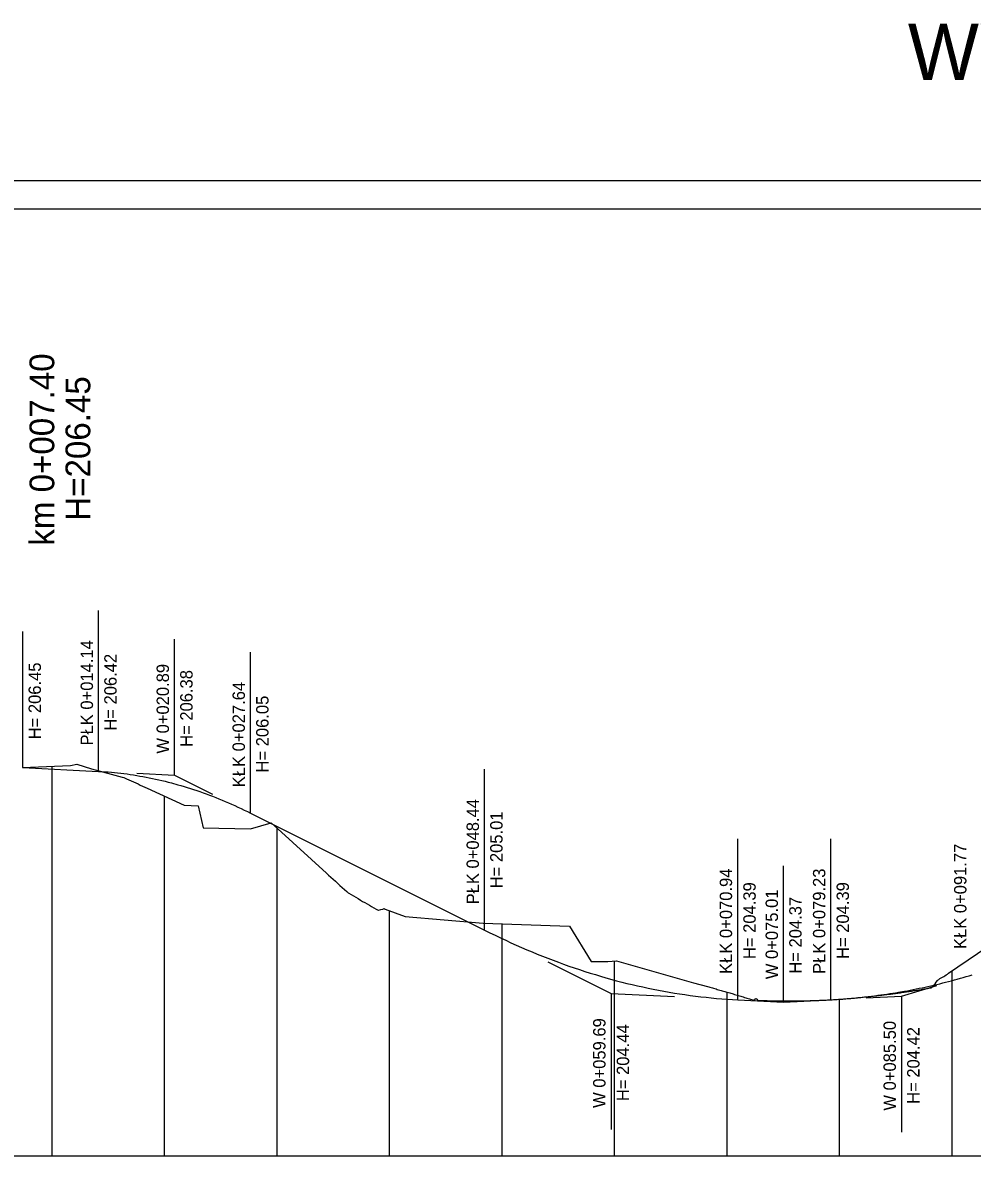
# Model space of a CAD drawing. Extents: x 6513080 to 6513380, y 6022307 to 6022469.
# Drawn here: x 6513125.1 to 6513209.5, y 6022367.3 to 6022469.3 of the extents above; entities that cross this region are included whole.
import ezdxf

# ---------------------------------------------------------------- set-up
doc = ezdxf.new("R2010")
doc.units = 0
for name, color, linetype in [('1', 7, 'Continuous'), ('42', 7, 'Continuous'), ('CONSTRUCTION_CLASS', 7, 'Continuous'), ('maxp_opisy', 7, 'Continuous'), ('maxp_ramka_2', 7, 'Continuous')]:
    doc.layers.add(name, color=color, linetype=linetype)

msp = doc.modelspace()

# ---------------------------------------------------------------- linework, layer by layer
for p, q in [((6513125.11, 6022403.07), (6513131.84, 6022402.73)), ((6513125.11, 6022403.07), (6513131.84, 6022402.73)), ((6513145.34, 6022399.02), (6513166.14, 6022388.62)), ((6513145.34, 6022399.02), (6513166.14, 6022388.62)), ((6513188.64, 6022382.43), (6513192.72, 6022382.23)), ((6513188.64, 6022382.43), (6513192.72, 6022382.23)), ((6513192.72, 6022382.23), (6513196.93, 6022382.44)), ((6513192.72, 6022382.23), (6513196.93, 6022382.44))]:
    msp.add_line(p, q)
for points in [[(6513131.84, 6022402.73), (6513132.12, 6022402.71), (6513132.41, 6022402.7), (6513132.69, 6022402.68), (6513132.97, 6022402.65), (6513133.25, 6022402.63), (6513133.53, 6022402.6), (6513133.81, 6022402.57), (6513134.09, 6022402.53), (6513134.37, 6022402.5), (6513134.65, 6022402.46), (6513134.94, 6022402.42), (6513135.22, 6022402.37), (6513135.5, 6022402.32), (6513135.78, 6022402.28), (6513136.06, 6022402.22), (6513136.34, 6022402.17), (6513136.62, 6022402.11), (6513136.9, 6022402.05), (6513137.19, 6022401.99), (6513137.47, 6022401.92), (6513137.75, 6022401.85), (6513138.03, 6022401.78), (6513138.31, 6022401.71), (6513138.87, 6022401.55), (6513139.15, 6022401.47), (6513139.43, 6022401.39), (6513139.72, 6022401.3), (6513140, 6022401.21), (6513140.28, 6022401.12), (6513140.56, 6022401.03), (6513140.84, 6022400.93), (6513141.12, 6022400.83), (6513141.4, 6022400.73), (6513141.68, 6022400.62), (6513141.97, 6022400.52), (6513142.25, 6022400.41), (6513142.53, 6022400.29), (6513142.81, 6022400.18), (6513143.09, 6022400.06), (6513143.37, 6022399.94), (6513143.65, 6022399.81), (6513143.93, 6022399.69), (6513144.21, 6022399.56), (6513144.5, 6022399.43), (6513144.78, 6022399.29), (6513145.06, 6022399.16), (6513145.34, 6022399.02)], [(6513131.84, 6022402.73), (6513132.12, 6022402.71), (6513132.41, 6022402.7), (6513132.69, 6022402.68), (6513132.97, 6022402.65), (6513133.25, 6022402.63), (6513133.53, 6022402.6), (6513133.81, 6022402.57), (6513134.09, 6022402.53), (6513134.37, 6022402.5), (6513134.65, 6022402.46), (6513134.94, 6022402.42), (6513135.22, 6022402.37), (6513135.5, 6022402.32), (6513135.78, 6022402.28), (6513136.06, 6022402.22), (6513136.34, 6022402.17), (6513136.62, 6022402.11), (6513136.9, 6022402.05), (6513137.19, 6022401.99), (6513137.47, 6022401.92), (6513137.75, 6022401.85), (6513138.03, 6022401.78), (6513138.31, 6022401.71), (6513138.87, 6022401.55), (6513139.15, 6022401.47), (6513139.43, 6022401.39), (6513139.72, 6022401.3), (6513140, 6022401.21), (6513140.28, 6022401.12), (6513140.56, 6022401.03), (6513140.84, 6022400.93), (6513141.12, 6022400.83), (6513141.4, 6022400.73), (6513141.68, 6022400.62), (6513141.97, 6022400.52), (6513142.25, 6022400.41), (6513142.53, 6022400.29), (6513142.81, 6022400.18), (6513143.09, 6022400.06), (6513143.37, 6022399.94), (6513143.65, 6022399.81), (6513143.93, 6022399.69), (6513144.21, 6022399.56), (6513144.5, 6022399.43), (6513144.78, 6022399.29), (6513145.06, 6022399.16), (6513145.34, 6022399.02)], [(6513166.14, 6022388.62), (6513166.61, 6022388.39), (6513167.08, 6022388.16), (6513167.55, 6022387.93), (6513168.02, 6022387.72), (6513168.49, 6022387.5), (6513168.96, 6022387.29), (6513169.42, 6022387.09), (6513169.89, 6022386.88), (6513170.36, 6022386.69), (6513170.83, 6022386.49), (6513171.3, 6022386.31), (6513171.77, 6022386.12), (6513172.24, 6022385.94), (6513172.7, 6022385.77), (6513173.17, 6022385.6), (6513173.64, 6022385.43), (6513174.11, 6022385.27), (6513174.58, 6022385.11), (6513175.05, 6022384.96), (6513175.52, 6022384.81), (6513175.99, 6022384.67), (6513176.45, 6022384.53), (6513176.92, 6022384.39), (6513177.86, 6022384.13), (6513178.33, 6022384.01), (6513178.8, 6022383.89), (6513179.27, 6022383.78), (6513179.73, 6022383.67), (6513180.2, 6022383.57), (6513180.67, 6022383.47), (6513181.14, 6022383.37), (6513181.61, 6022383.28), (6513182.08, 6022383.19), (6513182.55, 6022383.11), (6513183.01, 6022383.03), (6513183.48, 6022382.96), (6513183.95, 6022382.89), (6513184.42, 6022382.82), (6513184.89, 6022382.76), (6513185.36, 6022382.7), (6513185.83, 6022382.65), (6513186.29, 6022382.6), (6513186.76, 6022382.56), (6513187.23, 6022382.52), (6513187.7, 6022382.49), (6513188.17, 6022382.46), (6513188.64, 6022382.43)], [(6513166.14, 6022388.62), (6513166.61, 6022388.39), (6513167.08, 6022388.16), (6513167.55, 6022387.93), (6513168.02, 6022387.72), (6513168.49, 6022387.5), (6513168.96, 6022387.29), (6513169.42, 6022387.09), (6513169.89, 6022386.88), (6513170.36, 6022386.69), (6513170.83, 6022386.49), (6513171.3, 6022386.31), (6513171.77, 6022386.12), (6513172.24, 6022385.94), (6513172.7, 6022385.77), (6513173.17, 6022385.6), (6513173.64, 6022385.43), (6513174.11, 6022385.27), (6513174.58, 6022385.11), (6513175.05, 6022384.96), (6513175.52, 6022384.81), (6513175.99, 6022384.67), (6513176.45, 6022384.53), (6513176.92, 6022384.39), (6513177.86, 6022384.13), (6513178.33, 6022384.01), (6513178.8, 6022383.89), (6513179.27, 6022383.78), (6513179.73, 6022383.67), (6513180.2, 6022383.57), (6513180.67, 6022383.47), (6513181.14, 6022383.37), (6513181.61, 6022383.28), (6513182.08, 6022383.19), (6513182.55, 6022383.11), (6513183.01, 6022383.03), (6513183.48, 6022382.96), (6513183.95, 6022382.89), (6513184.42, 6022382.82), (6513184.89, 6022382.76), (6513185.36, 6022382.7), (6513185.83, 6022382.65), (6513186.29, 6022382.6), (6513186.76, 6022382.56), (6513187.23, 6022382.52), (6513187.7, 6022382.49), (6513188.17, 6022382.46), (6513188.64, 6022382.43)], [(6513196.93, 6022382.44), (6513197.19, 6022382.45), (6513197.45, 6022382.47), (6513197.71, 6022382.49), (6513197.97, 6022382.5), (6513198.24, 6022382.52), (6513198.5, 6022382.54), (6513198.76, 6022382.57), (6513199.02, 6022382.59), (6513199.28, 6022382.61), (6513199.54, 6022382.64), (6513199.8, 6022382.67), (6513200.06, 6022382.7), (6513200.33, 6022382.73), (6513200.59, 6022382.76), (6513200.85, 6022382.79), (6513201.11, 6022382.83), (6513201.37, 6022382.86), (6513201.63, 6022382.9), (6513201.89, 6022382.94), (6513202.15, 6022382.98), (6513202.42, 6022383.02), (6513202.68, 6022383.06), (6513202.94, 6022383.1), (6513203.46, 6022383.2), (6513203.72, 6022383.24), (6513203.98, 6022383.29), (6513204.24, 6022383.34), (6513204.51, 6022383.4), (6513204.77, 6022383.45), (6513205.03, 6022383.5), (6513205.29, 6022383.56), (6513205.55, 6022383.62), (6513205.81, 6022383.68), (6513206.07, 6022383.74), (6513206.34, 6022383.8), (6513206.6, 6022383.86), (6513206.86, 6022383.93), (6513207.12, 6022383.99), (6513207.38, 6022384.06), (6513207.64, 6022384.13), (6513207.9, 6022384.2), (6513208.16, 6022384.27), (6513208.43, 6022384.34), (6513208.69, 6022384.42), (6513208.95, 6022384.49), (6513209.21, 6022384.57), (6513209.47, 6022384.65)], [(6513196.93, 6022382.44), (6513197.19, 6022382.45), (6513197.45, 6022382.47), (6513197.71, 6022382.49), (6513197.97, 6022382.5), (6513198.24, 6022382.52), (6513198.5, 6022382.54), (6513198.76, 6022382.57), (6513199.02, 6022382.59), (6513199.28, 6022382.61), (6513199.54, 6022382.64), (6513199.8, 6022382.67), (6513200.06, 6022382.7), (6513200.33, 6022382.73), (6513200.59, 6022382.76), (6513200.85, 6022382.79), (6513201.11, 6022382.83), (6513201.37, 6022382.86), (6513201.63, 6022382.9), (6513201.89, 6022382.94), (6513202.15, 6022382.98), (6513202.42, 6022383.02), (6513202.68, 6022383.06), (6513202.94, 6022383.1), (6513203.46, 6022383.2), (6513203.72, 6022383.24), (6513203.98, 6022383.29), (6513204.24, 6022383.34), (6513204.51, 6022383.4), (6513204.77, 6022383.45), (6513205.03, 6022383.5), (6513205.29, 6022383.56), (6513205.55, 6022383.62), (6513205.81, 6022383.68), (6513206.07, 6022383.74), (6513206.34, 6022383.8), (6513206.6, 6022383.86), (6513206.86, 6022383.93), (6513207.12, 6022383.99), (6513207.38, 6022384.06), (6513207.64, 6022384.13), (6513207.9, 6022384.2), (6513208.16, 6022384.27), (6513208.43, 6022384.34), (6513208.69, 6022384.42), (6513208.95, 6022384.49), (6513209.21, 6022384.57), (6513209.47, 6022384.65)]]:
    msp.add_lwpolyline(points)
at = {"layer": '1'}
for p, q in [((6513127.7, 6022368.56), (6513127.7, 6022403.19)), ((6513135.22, 6022402.56), (6513138.59, 6022402.39)), ((6513138.59, 6022402.39), (6513141.97, 6022400.71)), ((6513137.7, 6022368.56), (6513137.7, 6022400.53)), ((6513147.7, 6022368.56), (6513147.7, 6022397.7)), ((6513157.7, 6022368.56), (6513157.7, 6022390.34)), ((6513167.7, 6022368.56), (6513167.7, 6022389.18)), ((6513177.7, 6022368.56), (6513177.7, 6022385.87)), ((6513171.77, 6022385.81), (6513177.39, 6022383)), ((6513207.7, 6022368.56), (6513207.7, 6022385)), ((6513177.39, 6022383), (6513183.01, 6022382.71)), ((6513187.7, 6022368.56), (6513187.7, 6022383.11)), ((6513203.2, 6022382.76), (6513206.34, 6022383.7)), ((6513197.7, 6022368.56), (6513197.7, 6022382.49)), ((6513200.06, 6022382.6), (6513203.2, 6022382.76)), ((6513127.7, 6022368.56), (6513127.7, 6022369.56)), ((6513137.7, 6022368.56), (6513137.7, 6022369.56)), ((6513147.7, 6022368.56), (6513147.7, 6022369.56)), ((6513157.7, 6022368.56), (6513157.7, 6022369.56)), ((6513167.7, 6022368.56), (6513167.7, 6022369.56)), ((6513177.7, 6022368.56), (6513177.7, 6022369.56)), ((6513187.7, 6022368.56), (6513187.7, 6022369.56)), ((6513197.7, 6022368.56), (6513197.7, 6022369.56)), ((6513207.7, 6022368.56), (6513207.7, 6022369.56)), ((6513117.7, 6022368.56), (6513327.7, 6022368.56))]:
    msp.add_line(p, q, dxfattribs=at)
msp.add_lwpolyline([(6513125.08, 6022403.07), (6513129.34, 6022403.24), (6513129.9, 6022403.38), (6513131.2, 6022402.95), (6513133.93, 6022402.23), (6513134.09, 6022402.19), (6513134.13, 6022402.17), (6513134.33, 6022402.08), (6513134.53, 6022401.99), (6513134.74, 6022401.89), (6513134.94, 6022401.8), (6513135.14, 6022401.71), (6513135.34, 6022401.62), (6513135.54, 6022401.52), (6513135.74, 6022401.43), (6513135.94, 6022401.34), (6513136.15, 6022401.24), (6513139.43, 6022399.72), (6513140.7, 6022399.68), (6513141.13, 6022397.7), (6513145.35, 6022397.63), (6513147.18, 6022398.17), (6513147.78, 6022397.63), (6513152.08, 6022393.69), (6513152.28, 6022393.51), (6513152.48, 6022393.33), (6513152.69, 6022393.15), (6513152.89, 6022392.96), (6513153.09, 6022392.78), (6513153.29, 6022392.6), (6513153.49, 6022392.42), (6513153.69, 6022392.24), (6513153.89, 6022392.06), (6513154.03, 6022391.94), (6513154.09, 6022391.9), (6513154.29, 6022391.78), (6513154.49, 6022391.66), (6513154.7, 6022391.54), (6513154.9, 6022391.42), (6513155.1, 6022391.3), (6513155.3, 6022391.18), (6513155.5, 6022391.07), (6513155.7, 6022390.95), (6513155.9, 6022390.84), (6513156.1, 6022390.72), (6513156.3, 6022390.61), (6513156.5, 6022390.5), (6513156.69, 6022390.39), (6513156.71, 6022390.4), (6513156.91, 6022390.45), (6513157.11, 6022390.5), (6513157.22, 6022390.53), (6513157.31, 6022390.49), (6513159.07, 6022389.82), (6513166.02, 6022389.23), (6513173.68, 6022388.98), (6513175.61, 6022385.83), (6513177.11, 6022385.82), (6513177.88, 6022385.89), (6513184.7, 6022383.94), (6513185.95, 6022383.61), (6513186.06, 6022383.58), (6513186.17, 6022383.55), (6513186.28, 6022383.52), (6513186.39, 6022383.49), (6513186.5, 6022383.46), (6513186.61, 6022383.43), (6513186.72, 6022383.4), (6513186.83, 6022383.36), (6513186.94, 6022383.33), (6513187.05, 6022383.3), (6513187.16, 6022383.27), (6513187.27, 6022383.24), (6513187.38, 6022383.21), (6513187.49, 6022383.18), (6513187.6, 6022383.14), (6513187.71, 6022383.11), (6513187.82, 6022383.08), (6513187.93, 6022383.05), (6513188.04, 6022383.01), (6513188.15, 6022382.98), (6513188.25, 6022382.95), (6513188.36, 6022382.91), (6513188.47, 6022382.88), (6513188.58, 6022382.85), (6513188.69, 6022382.81), (6513188.8, 6022382.78), (6513188.91, 6022382.74), (6513189.02, 6022382.71), (6513189.13, 6022382.68), (6513189.24, 6022382.64), (6513189.35, 6022382.61), (6513189.37, 6022382.6), (6513189.46, 6022382.58), (6513189.57, 6022382.54), (6513189.68, 6022382.51), (6513189.79, 6022382.48), (6513189.9, 6022382.45), (6513190.01, 6022382.42), (6513190.05, 6022382.41), (6513190.12, 6022382.4), (6513190.14, 6022382.4), (6513190.23, 6022382.51), (6513190.28, 6022382.56), (6513190.34, 6022382.49), (6513190.44, 6022382.38), (6513190.45, 6022382.38), (6513190.56, 6022382.38), (6513190.67, 6022382.37), (6513190.78, 6022382.37), (6513190.89, 6022382.37), (6513191, 6022382.36), (6513191.11, 6022382.36), (6513191.22, 6022382.36), (6513191.33, 6022382.35), (6513191.44, 6022382.35), (6513191.55, 6022382.35), (6513191.66, 6022382.34), (6513191.77, 6022382.34), (6513191.88, 6022382.34), (6513191.99, 6022382.34), (6513192.1, 6022382.34), (6513192.21, 6022382.33), (6513192.32, 6022382.33), (6513192.43, 6022382.33), (6513192.54, 6022382.33), (6513192.65, 6022382.33), (6513192.76, 6022382.33), (6513192.87, 6022382.33), (6513192.98, 6022382.33), (6513193.09, 6022382.33), (6513193.2, 6022382.33), (6513193.31, 6022382.33), (6513193.42, 6022382.33), (6513193.53, 6022382.33), (6513193.64, 6022382.33), (6513193.75, 6022382.33), (6513193.86, 6022382.33), (6513193.97, 6022382.33), (6513194.08, 6022382.33), (6513194.19, 6022382.34), (6513194.3, 6022382.34), (6513194.41, 6022382.34), (6513194.52, 6022382.34), (6513194.63, 6022382.34), (6513194.74, 6022382.35), (6513194.85, 6022382.35), (6513194.96, 6022382.35), (6513195.07, 6022382.36), (6513195.18, 6022382.36), (6513195.29, 6022382.36), (6513195.4, 6022382.37), (6513195.51, 6022382.37), (6513195.62, 6022382.37), (6513195.73, 6022382.38), (6513195.84, 6022382.38), (6513195.95, 6022382.39), (6513196.06, 6022382.39), (6513196.17, 6022382.4), (6513196.28, 6022382.4), (6513196.39, 6022382.41), (6513196.5, 6022382.41), (6513196.61, 6022382.42), (6513196.72, 6022382.43), (6513196.83, 6022382.43), (6513196.94, 6022382.44), (6513197.05, 6022382.44), (6513197.16, 6022382.45), (6513197.27, 6022382.46), (6513197.38, 6022382.47), (6513197.49, 6022382.47), (6513197.6, 6022382.48), (6513197.71, 6022382.49), (6513197.82, 6022382.5), (6513197.93, 6022382.5), (6513198.04, 6022382.51), (6513198.15, 6022382.52), (6513198.26, 6022382.53), (6513198.37, 6022382.54), (6513198.48, 6022382.55), (6513198.59, 6022382.55), (6513198.7, 6022382.56), (6513198.81, 6022382.57), (6513198.92, 6022382.58), (6513199.03, 6022382.59), (6513199.14, 6022382.6), (6513199.25, 6022382.61), (6513199.36, 6022382.62), (6513199.47, 6022382.63), (6513199.58, 6022382.64), (6513199.69, 6022382.65), (6513199.8, 6022382.66), (6513199.91, 6022382.68), (6513200.02, 6022382.69), (6513200.13, 6022382.7), (6513200.24, 6022382.71), (6513200.35, 6022382.72), (6513200.46, 6022382.73), (6513200.57, 6022382.74), (6513200.68, 6022382.76), (6513200.79, 6022382.77), (6513200.9, 6022382.78), (6513201.01, 6022382.79), (6513201.12, 6022382.81), (6513201.23, 6022382.82), (6513201.34, 6022382.83), (6513201.45, 6022382.85), (6513201.56, 6022382.86), (6513201.67, 6022382.87), (6513201.78, 6022382.89), (6513201.89, 6022382.9), (6513202, 6022382.92), (6513202.11, 6022382.93), (6513202.22, 6022382.94), (6513202.33, 6022382.96), (6513202.44, 6022382.97), (6513202.55, 6022382.99), (6513202.66, 6022383), (6513202.77, 6022383.02), (6513202.88, 6022383.03), (6513202.99, 6022383.05), (6513203.1, 6022383.06), (6513203.21, 6022383.08), (6513203.32, 6022383.1), (6513203.43, 6022383.11), (6513203.54, 6022383.13), (6513203.65, 6022383.14), (6513203.76, 6022383.16), (6513203.87, 6022383.18), (6513203.98, 6022383.19), (6513204.09, 6022383.21), (6513204.2, 6022383.23), (6513204.31, 6022383.25), (6513204.42, 6022383.26), (6513204.53, 6022383.28), (6513204.64, 6022383.3), (6513204.75, 6022383.32), (6513204.86, 6022383.33), (6513204.97, 6022383.35), (6513205.08, 6022383.37), (6513205.19, 6022383.39), (6513205.3, 6022383.41), (6513205.41, 6022383.42), (6513205.52, 6022383.44), (6513205.63, 6022383.46), (6513205.74, 6022383.48), (6513205.85, 6022383.5), (6513205.9, 6022383.51), (6513205.96, 6022383.58), (6513206.07, 6022383.72), (6513206.18, 6022383.85), (6513206.29, 6022383.99), (6513206.4, 6022384.14), (6513206.46, 6022384.21), (6513206.51, 6022384.24), (6513206.62, 6022384.31), (6513206.73, 6022384.37), (6513206.84, 6022384.44), (6513206.95, 6022384.5), (6513207.06, 6022384.57), (6513207.17, 6022384.64), (6513207.28, 6022384.72), (6513207.39, 6022384.79), (6513214.28, 6022389.47)], dxfattribs=at)
at = {"layer": '42'}
for p, q in [((6513131.84, 6022402.73), (6513131.84, 6022417.03)), ((6513125.11, 6022403.07), (6513125.11, 6022415.17)), ((6513138.59, 6022402.39), (6513138.59, 6022414.49)), ((6513145.34, 6022399.02), (6513145.34, 6022413.32)), ((6513125.11, 6022403.07), (6513131.84, 6022402.73)), ((6513166.14, 6022388.62), (6513166.14, 6022402.92)), ((6513145.34, 6022399.02), (6513166.14, 6022388.62)), ((6513188.64, 6022382.43), (6513188.64, 6022396.73)), ((6513196.93, 6022382.44), (6513196.93, 6022396.74)), ((6513192.72, 6022382.23), (6513192.72, 6022394.33)), ((6513177.39, 6022383), (6513177.39, 6022370.9)), ((6513188.64, 6022382.43), (6513192.72, 6022382.23)), ((6513192.72, 6022382.23), (6513196.93, 6022382.44)), ((6513203.2, 6022382.76), (6513203.2, 6022370.66))]:
    msp.add_line(p, q, dxfattribs=at)
for points in [[(6513131.84, 6022402.73), (6513132.12, 6022402.71), (6513132.41, 6022402.7), (6513132.69, 6022402.68), (6513132.97, 6022402.65), (6513133.25, 6022402.63), (6513133.53, 6022402.6), (6513133.81, 6022402.57), (6513134.09, 6022402.53), (6513134.37, 6022402.5), (6513134.65, 6022402.46), (6513134.94, 6022402.42), (6513135.22, 6022402.37), (6513135.5, 6022402.32), (6513135.78, 6022402.28), (6513136.06, 6022402.22), (6513136.34, 6022402.17), (6513136.62, 6022402.11), (6513136.9, 6022402.05), (6513137.19, 6022401.99), (6513137.47, 6022401.92), (6513137.75, 6022401.85), (6513138.03, 6022401.78), (6513138.31, 6022401.71), (6513138.87, 6022401.55), (6513139.15, 6022401.47), (6513139.43, 6022401.39), (6513139.72, 6022401.3), (6513140, 6022401.21), (6513140.28, 6022401.12), (6513140.56, 6022401.03), (6513140.84, 6022400.93), (6513141.12, 6022400.83), (6513141.4, 6022400.73), (6513141.68, 6022400.62), (6513141.97, 6022400.52), (6513142.25, 6022400.41), (6513142.53, 6022400.29), (6513142.81, 6022400.18), (6513143.09, 6022400.06), (6513143.37, 6022399.94), (6513143.65, 6022399.81), (6513143.93, 6022399.69), (6513144.21, 6022399.56), (6513144.5, 6022399.43), (6513144.78, 6022399.29), (6513145.06, 6022399.16), (6513145.34, 6022399.02)], [(6513166.14, 6022388.62), (6513166.61, 6022388.39), (6513167.08, 6022388.16), (6513167.55, 6022387.93), (6513168.02, 6022387.72), (6513168.49, 6022387.5), (6513168.96, 6022387.29), (6513169.42, 6022387.09), (6513169.89, 6022386.88), (6513170.36, 6022386.69), (6513170.83, 6022386.49), (6513171.3, 6022386.31), (6513171.77, 6022386.12), (6513172.24, 6022385.94), (6513172.7, 6022385.77), (6513173.17, 6022385.6), (6513173.64, 6022385.43), (6513174.11, 6022385.27), (6513174.58, 6022385.11), (6513175.05, 6022384.96), (6513175.52, 6022384.81), (6513175.99, 6022384.67), (6513176.45, 6022384.53), (6513176.92, 6022384.39), (6513177.86, 6022384.13), (6513178.33, 6022384.01), (6513178.8, 6022383.89), (6513179.27, 6022383.78), (6513179.73, 6022383.67), (6513180.2, 6022383.57), (6513180.67, 6022383.47), (6513181.14, 6022383.37), (6513181.61, 6022383.28), (6513182.08, 6022383.19), (6513182.55, 6022383.11), (6513183.01, 6022383.03), (6513183.48, 6022382.96), (6513183.95, 6022382.89), (6513184.42, 6022382.82), (6513184.89, 6022382.76), (6513185.36, 6022382.7), (6513185.83, 6022382.65), (6513186.29, 6022382.6), (6513186.76, 6022382.56), (6513187.23, 6022382.52), (6513187.7, 6022382.49), (6513188.17, 6022382.46), (6513188.64, 6022382.43)], [(6513196.93, 6022382.44), (6513197.19, 6022382.45), (6513197.45, 6022382.47), (6513197.71, 6022382.49), (6513197.97, 6022382.5), (6513198.24, 6022382.52), (6513198.5, 6022382.54), (6513198.76, 6022382.57), (6513199.02, 6022382.59), (6513199.28, 6022382.61), (6513199.54, 6022382.64), (6513199.8, 6022382.67), (6513200.06, 6022382.7), (6513200.33, 6022382.73), (6513200.59, 6022382.76), (6513200.85, 6022382.79), (6513201.11, 6022382.83), (6513201.37, 6022382.86), (6513201.63, 6022382.9), (6513201.89, 6022382.94), (6513202.15, 6022382.98), (6513202.42, 6022383.02), (6513202.68, 6022383.06), (6513202.94, 6022383.1), (6513203.46, 6022383.2), (6513203.72, 6022383.24), (6513203.98, 6022383.29), (6513204.24, 6022383.34), (6513204.51, 6022383.4), (6513204.77, 6022383.45), (6513205.03, 6022383.5), (6513205.29, 6022383.56), (6513205.55, 6022383.62), (6513205.81, 6022383.68), (6513206.07, 6022383.74), (6513206.34, 6022383.8), (6513206.6, 6022383.86), (6513206.86, 6022383.93), (6513207.12, 6022383.99), (6513207.38, 6022384.06), (6513207.64, 6022384.13), (6513207.9, 6022384.2), (6513208.16, 6022384.27), (6513208.43, 6022384.34), (6513208.69, 6022384.42), (6513208.95, 6022384.49), (6513209.21, 6022384.57), (6513209.47, 6022384.65)]]:
    msp.add_lwpolyline(points, dxfattribs=at)
at = {"layer": 'maxp_ramka_2'}
for points in [[(6513079.9, 6022455.24), (6513379.9, 6022455.24), (6513379.9, 6022306.74), (6513079.9, 6022306.74)], [(6513092.4, 6022309.24), (6513092.4, 6022452.74), (6513377.4, 6022452.74), (6513377.4, 6022309.24)]]:
    msp.add_lwpolyline(points, close=True, dxfattribs=at)

# ---------------------------------------------------------------- texts
at = {"layer": '42'}
for s, p in [('PŁK 0+014.14', (6513131.34, 6022405.03)), ('H= 206.42', (6513133.44, 6022406.35)), ('H= 206.45', (6513126.71, 6022405.58)), ('W 0+020.89', (6513138.09, 6022404.31)), ('H= 206.38', (6513140.19, 6022404.91)), ('KŁK 0+027.64', (6513144.84, 6022401.32)), ('H= 206.05', (6513146.94, 6022402.63)), ('PŁK 0+048.44', (6513165.64, 6022390.91)), ('H= 205.01', (6513167.74, 6022392.34)), ('KŁK 0+091.77', (6513208.97, 6022386.94)), ('KŁK 0+070.94', (6513188.14, 6022384.73)), ('PŁK 0+079.23', (6513196.43, 6022384.73)), ('H= 204.39', (6513190.24, 6022386.05)), ('W 0+075.01', (6513192.22, 6022384.26)), ('H= 204.39', (6513198.53, 6022386.06)), ('H= 204.37', (6513194.32, 6022384.75)), ('W 0+059.69', (6513176.89, 6022372.82)), ('H= 204.44', (6513178.99, 6022373.42)), ('W 0+085.50', (6513202.7, 6022372.58)), ('H= 204.42', (6513204.8, 6022373.18))]:
    msp.add_text(s, height=1.1, rotation=90, dxfattribs=at).set_placement(p)
at = {"layer": 'CONSTRUCTION_CLASS'}
msp.add_text('WYKONAWCZY', height=5, rotation=0.0002, dxfattribs=at).set_placement((6513203.77, 6022464.18))
at = {"layer": 'maxp_opisy'}
for s, p in [('km 0+007.40', (6513127.9, 6022422.79)), ('H=206.45', (6513131.1, 6022425.01))]:
    msp.add_text(s, height=2.2, rotation=90.0162, dxfattribs=at).set_placement(p)

doc.saveas('drawing.dxf')
